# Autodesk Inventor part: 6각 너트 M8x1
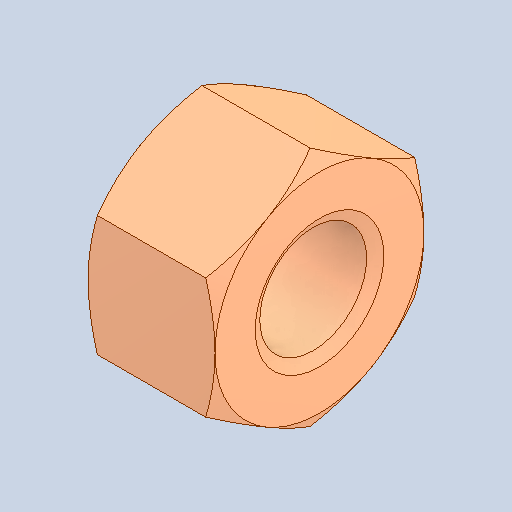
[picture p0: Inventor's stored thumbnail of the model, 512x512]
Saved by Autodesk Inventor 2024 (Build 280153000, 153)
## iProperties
Created: 2025-10
Part Number: 6각 너트 M8x1
Material: 강철, 연강
Description: 6각 너트 및 6각 가는 너트
Document SubType Name: Modeling
Designer: EDU03
Density: 7.85 g/cm^3
Appearance: 기본값
Author: jhkim
Sending System: Autodesk Inventor 2026
Preprocessor: ST-DEVELOPER v20.1
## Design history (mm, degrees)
feature "Solid1"
node "솔리드1"
